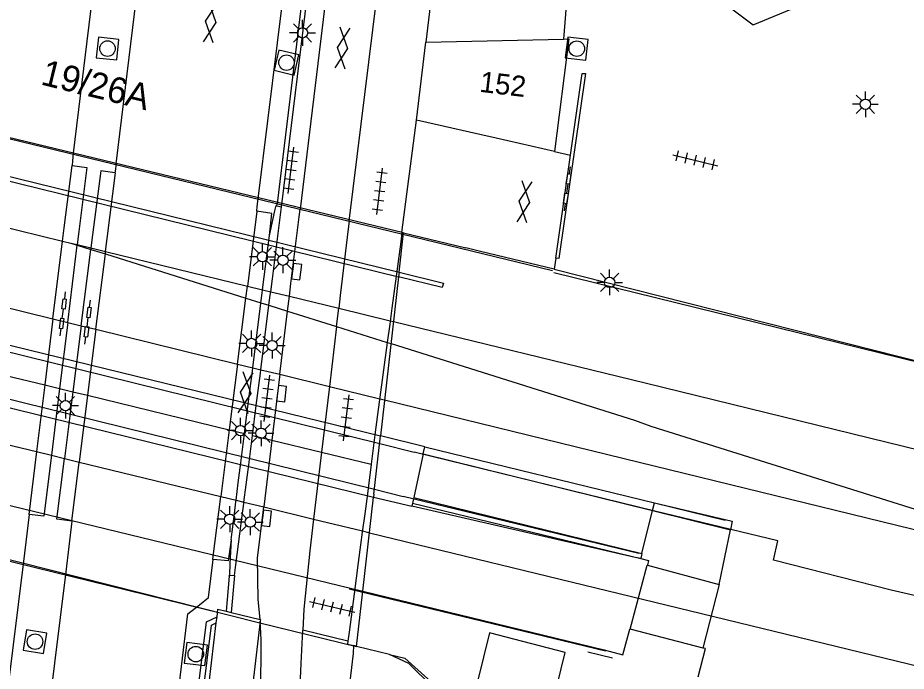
# Model space of a CAD drawing. Extents: x 131000 to 133014, y 396499 to 399001.
# Drawn here: x 131700.07 to 131743.05, y 397381.73 to 397413.33 of the extents above; entities that cross this region are included whole.
import ezdxf

# ---------------------------------------------------------------- set-up
doc = ezdxf.new("R2010")
doc.units = 0
for name, color, linetype in [('gg-afsc-hekwerk', 7, 'Continuous'), ('gg-afsc-muur', 7, 'Continuous'), ('gg-anno-huisnummerreeks BGT', 7, 'Continuous'), ('gg-aspt-spoorlijn', 7, 'Continuous'), ('gg-bbg-hoofdgebouw', 7, 'Continuous'), ('gg-bbg-overig bouwwerk', 7, 'Continuous'), ('gg-knt-bronhoudergrens', 7, 'Continuous'), ('gg-knt-bronhoudergrens niveau 01', 7, 'Continuous'), ('gg-knt-trap', 7, 'Continuous'), ('gg-knt-verharding', 7, 'Continuous'), ('gg-knt-verharding niveau 01', 7, 'Continuous'), ('gg-knt-verharding nz', 7, 'Continuous'), ('gg-kntw-beschoeiing', 7, 'Continuous'), ('gg-kwrk-kunstwerk', 7, 'Continuous'), ('gg-kwrk-kunstwerk niveau 01', 7, 'Continuous'), ('gt-anno-nummer portaalmast', 7, 'Continuous'), ('gt-grn-afwateringsgoot', 7, 'Continuous'), ('gt-grn-bladgrens', 7, 'Continuous'), ('gt-grn-weggrens', 7, 'Continuous'), ('gt-symb-afwateringsgoot', 7, 'Continuous'), ('gt-symb-gesloten verharding', 7, 'Continuous'), ('gt-symb-kolk', 7, 'Continuous'), ('gt-symb-lichtmast', 7, 'Continuous'), ('gt-symb-rioolschacht', 7, 'Continuous'), ('gt-symb-tegel verharding', 7, 'Continuous'), ('gx-grn-maaiveld', 7, 'Continuous'), ('gx-knt-lijn weginrichtingselement', 7, 'Continuous')]:
    doc.layers.add(name, color=color, linetype=linetype)

# ---------------------------------------------------------------- blocks, each defined once
blk = doc.blocks.new('gt0-LMAST')
at = {"layer": 'gt-symb-lichtmast'}
for p, q in [((-0.182, 0.173), (-0.447, 0.438)), ((-0.005, 0.246), (-0.005, 0.621)), ((0.172, 0.173), (0.437, 0.438)), ((-0.255, -0.004), (-0.63, -0.004)), ((-0.182, -0.181), (-0.447, -0.446)), ((-0.005, -0.254), (-0.005, -0.629)), ((0.437, -0.446), (0.172, -0.181)), ((0.245, -0.004), (0.62, -0.004))]:
    blk.add_line(p, q, dxfattribs=at)
blk.add_circle((-0.005, -0.004), 0.25, dxfattribs=at)
blk = doc.blocks.new('gt0-RS')
at = {"layer": 'gt-symb-rioolschacht'}
blk.add_lwpolyline([(-0.5, -0.5), (0.5, -0.5), (0.5, 0.5), (-0.5, 0.5)], close=True, dxfattribs=at)
blk.add_circle((0, 0), 0.375, dxfattribs=at)
blk = doc.blocks.new('gt0-GESVH1')
at = {"layer": 'gt-symb-gesloten verharding'}
for p, q in [((-0.992, -0.261), (0.008, 0.239)), ((0.008, -0.261), (-0.992, 0.239)), ((0.008, 0.239), (1.008, -0.261)), ((1.008, 0.239), (0.008, -0.261))]:
    blk.add_line(p, q, dxfattribs=at)
blk = doc.blocks.new('gt0-AFWGT_1')
at = {"layer": 'gt-symb-afwateringsgoot'}
for p, q in [((-1.076, 0), (-0.726, 0)), ((-0.225, 0), (0.225, 0)), ((0.725, 0), (1.075, 0))]:
    blk.add_line(p, q, dxfattribs=at)
for points in [[(-0.726, 0.075), (-0.225, 0.075), (-0.225, -0.075), (-0.726, -0.075)], [(0.225, 0.075), (0.725, 0.075), (0.725, -0.075), (0.225, -0.075)]]:
    blk.add_lwpolyline(points, close=True, dxfattribs=at)
blk = doc.blocks.new('gt0-TEG1')
at = {"layer": 'gt-symb-tegel verharding'}
for p, q in [((-1.125, 0), (1.125, 0)), ((-0.9, -0.25), (-0.9, 0.25)), ((-0.45, -0.25), (-0.45, 0.25)), ((0, -0.25), (0, 0.25)), ((0.45, -0.25), (0.45, 0.25)), ((0.9, -0.25), (0.9, 0.25))]:
    blk.add_line(p, q, dxfattribs=at)
blk = doc.blocks.new('gt0-KOLK')
at = {"layer": 'gt-symb-kolk'}
blk.add_lwpolyline([(0, 0), (0.375, 0), (0.375, 0.4), (-0.375, 0.4), (-0.375, 0), (0, 0)], dxfattribs=at)

msp = doc.modelspace()

# ---------------------------------------------------------------- linework, layer by layer
at = {"layer": 'gg-afsc-hekwerk'}
for p, q in [((131717.574, 397392.739), (131719.242, 397392.327)), ((131717.324, 397390.534), (131718.712, 397390.175)), ((131730.112, 397387.429), (131718.712, 397390.175)), ((131727.643, 397382.676), (131728.841, 397382.383))]:
    msp.add_line(p, q, dxfattribs=at)
for points in [[(131773.803, 397387.731), (131764.361, 397390.805), (131762.176, 397392.112), (131757.298, 397393.292), (131742.728, 397396.881), (131725.995, 397401.003)], [(131736.842, 397388.039), (131730.884, 397389.465), (131719.242, 397392.327)], [(131779.947, 397376.463), (131765.767, 397379.945), (131756.358, 397382.28), (131749.326, 397384.036), (131749.202, 397383.503), (131747.851, 397383.857), (131747.991, 397384.345), (131742.325, 397385.649), (131736.618, 397387.108), (131736.842, 397388.039)]]:
    msp.add_lwpolyline(points, dxfattribs=at)
at = {"layer": 'gg-afsc-muur'}
for p, q in [((131714.708, 397421.488), (131712.611, 397404.357)), ((131712.841, 397404.301), (131714.948, 397421.519)), ((131712.597, 397404.241), (131712.611, 397404.357)), ((131712.597, 397404.241), (131712.827, 397404.189)), ((131712.794, 397403.932), (131712.827, 397404.189)), ((131712.827, 397404.189), (131712.841, 397404.301)), ((131712.384, 397400.707), (131712.794, 397403.932)), ((131712.305, 397400.085), (131712.384, 397400.707)), ((131712.22, 397399.429), (131712.283, 397399.917)), ((131712.283, 397399.917), (131712.305, 397400.085)), ((131711.825, 397396.315), (131712.22, 397399.429)), ((131711.727, 397395.554), (131711.804, 397396.153)), ((131711.804, 397396.153), (131711.825, 397396.315)), ((131711.603, 397394.576), (131711.727, 397395.554)), ((131711.42, 397393.137), (131711.603, 397394.576)), ((131711.239, 397391.712), (131711.42, 397393.137)), ((131719.755, 397392.586), (131730.865, 397389.872)), ((131711.116, 397390.748), (131711.239, 397391.712)), ((131711.009, 397389.91), (131711.116, 397390.748)), ((131711, 397389.837), (131711.009, 397389.91)), ((131710.925, 397389.247), (131711, 397389.837)), ((131719.169, 397389.865), (131730.201, 397387.176)), ((131730.865, 397389.872), (131734.291, 397389.035)), ((131710.814, 397388.376), (131710.925, 397389.247)), ((131710.623, 397386.875), (131710.814, 397388.376)), ((131710.557, 397386.362), (131710.623, 397386.875)), ((131710.301, 397386.326), (131710.148, 397384.633)), ((131710.301, 397386.326), (131710.302, 397386.375)), ((131710.557, 397386.362), (131710.394, 397384.572)), ((131716.099, 397385.714), (131728.496, 397382.719))]:
    msp.add_line(p, q, dxfattribs=at)
for points in [[(131707.202, 397367.988), (131709.204, 397384.118), (131709.705, 397384.368)], [(131707.723, 397370.16), (131709.436, 397383.954), (131709.67, 397384.071)]]:
    msp.add_lwpolyline(points, dxfattribs=at)
at = {"layer": 'gg-aspt-spoorlijn'}
for p, q in [((131698.809, 397403.367), (131702.237, 397402.535)), ((131702.237, 397402.535), (131702.639, 397402.437)), ((131702.639, 397402.437), (131702.946, 397402.362)), ((131702.639, 397402.437), (131702.943, 397402.341)), ((131702.946, 397402.362), (131703.609, 397402.201)), ((131702.943, 397402.341), (131703.601, 397402.135)), ((131703.601, 397402.135), (131704.303, 397401.914)), ((131703.609, 397402.201), (131704.317, 397402.029)), ((131704.317, 397402.029), (131711.176, 397400.36)), ((131704.303, 397401.914), (131711.104, 397399.779)), ((131711.176, 397400.36), (131711.908, 397400.182)), ((131711.908, 397400.182), (131712.305, 397400.085)), ((131712.305, 397400.085), (131713.206, 397399.866)), ((131713.206, 397399.866), (131715.594, 397399.285)), ((131698.338, 397399.615), (131701.77, 397398.775)), ((131711.104, 397399.779), (131711.829, 397399.551)), ((131711.829, 397399.551), (131712.22, 397399.429)), ((131712.22, 397399.429), (131713.118, 397399.147)), ((131713.118, 397399.147), (131715.489, 397398.402)), ((131715.594, 397399.285), (131718.081, 397398.68)), ((131701.77, 397398.775), (131702.484, 397398.601)), ((131702.484, 397398.601), (131703.135, 397398.442)), ((131718.081, 397398.68), (131718.245, 397398.64)), ((131718.245, 397398.64), (131730.419, 397395.679)), ((131703.135, 397398.442), (131703.847, 397398.267)), ((131703.847, 397398.267), (131710.701, 397396.59)), ((131715.489, 397398.402), (131717.941, 397397.632)), ((131717.941, 397397.632), (131718.124, 397397.575)), ((131718.124, 397397.575), (131729.909, 397393.874)), ((131710.701, 397396.59), (131711.434, 397396.411)), ((131711.434, 397396.411), (131711.825, 397396.315)), ((131711.825, 397396.315), (131712.741, 397396.091)), ((131712.741, 397396.091), (131715.144, 397395.503)), ((131715.144, 397395.503), (131717.578, 397394.908)), ((131717.578, 397394.908), (131717.814, 397394.85)), ((131717.814, 397394.85), (131730.13, 397391.837)), ((131729.909, 397393.874), (131730.687, 397393.578)), ((131730.687, 397393.578), (131757.904, 397385.057)), ((131697.533, 397393.187), (131700.973, 397392.351)), ((131700.973, 397392.351), (131701.694, 397392.175)), ((131701.694, 397392.175), (131702.323, 397392.022)), ((131702.323, 397392.022), (131703.042, 397391.847)), ((131703.042, 397391.847), (131709.893, 397390.181)), ((131730.13, 397391.837), (131757.904, 397385.057)), ((131709.893, 397390.181), (131710.63, 397390.002)), ((131710.63, 397390.002), (131711.009, 397389.91)), ((131711.009, 397389.91), (131711.966, 397389.677)), ((131711.966, 397389.677), (131714.38, 397389.09)), ((131714.38, 397389.09), (131716.741, 397388.515)), ((131716.741, 397388.515), (131717.084, 397388.432)), ((131717.084, 397388.432), (131729.758, 397385.349)), ((131729.758, 397385.349), (131733.135, 397384.528))]:
    msp.add_line(p, q, dxfattribs=at)
for points in [[(131730.419, 397395.679), (131868.942, 397361.737), (131903.166, 397353.165), (132046.719, 397318.202), (132097.768, 397305.577)], [(131733.135, 397384.528), (131744.941, 397381.656), (131764.841, 397376.893), (131798.667, 397369.303), (131817.252, 397364.815)]]:
    msp.add_lwpolyline(points, dxfattribs=at)
at = {"layer": 'gg-bbg-hoofdgebouw'}
for p, q in [((131719.8, 397412.16), (131726.47, 397412.304)), ((131726.73, 397412.31), (131726.03, 397406.86)), ((131726.47, 397412.304), (131726.73, 397412.31)), ((131719.36, 397408.39), (131719.8, 397412.16)), ((131722.417, 397407.689), (131719.36, 397408.39)), ((131723.214, 397407.506), (131722.417, 397407.689)), ((131726.03, 397406.86), (131723.214, 397407.506))]:
    msp.add_line(p, q, dxfattribs=at)
at = {"layer": 'gg-bbg-overig bouwwerk'}
msp.add_lwpolyline([(131722.88, 397383.583), (131722.302, 397381.233), (131725.989, 397380.33), (131726.555, 397382.643), (131722.88, 397383.583)], dxfattribs=at)
at = {"layer": 'gg-knt-bronhoudergrens'}
msp.add_line((131716.017, 397383.044), (131716.324, 397382.969), dxfattribs=at)
msp.add_lwpolyline([(131718.048, 397382.549), (131718.789, 397382.368), (131721.171, 397380.227)], dxfattribs=at)
at = {"layer": 'gg-knt-bronhoudergrens niveau 01'}
msp.add_line((131718.733, 397402.927), (131689.368, 397410.01), dxfattribs=at)
at = {"layer": 'gg-knt-trap'}
for p, q in [((131726.03, 397406.86), (131726.806, 397406.682)), ((131726.093, 397401.715), (131726.016, 397401.17)), ((131709.67, 397384.071), (131709.705, 397384.368)), ((131710.148, 397384.633), (131710.394, 397384.572)), ((131710.394, 397384.572), (131711.791, 397384.228))]:
    msp.add_line(p, q, dxfattribs=at)
for points in [[(131709.705, 397384.368), (131709.748, 397384.731), (131710.148, 397384.633)], [(131711.796, 397384.157), (131710.726, 397375.111), (131708.647, 397375.372), (131709.67, 397384.071)], [(131711.791, 397384.228), (131711.804, 397384.225), (131711.796, 397384.157)]]:
    msp.add_lwpolyline(points, dxfattribs=at)
at = {"layer": 'gg-knt-verharding'}
for p, q in [((131716.096, 397403.5), (131718.375, 397421.956)), ((131715.852, 397421.635), (131713.726, 397404.083)), ((131704.819, 397406.276), (131706.556, 397420.446)), ((131704.367, 397420.167), (131702.743, 397406.787)), ((131720.2, 397415.449), (131719.8, 397412.16)), ((131726.672, 397414.918), (131726.47, 397412.304)), ((131726.016, 397401.17), (131762.283, 397392.002))]:
    msp.add_line(p, q, dxfattribs=at)
for points in [[(131741.8, 397421.13), (131737.08, 397424.63), (131731.68, 397422.35), (131730.97, 397416.51), (131735.64, 397412.99), (131741.08, 397415.25), (131741.8, 397421.13)], [(131711.693, 397404.584), (131713.103, 397415.907), (131713.773, 397421.369)], [(131700.341, 397387.044), (131697.077, 397360.779), (131692.466, 397323.47)], [(131702.391, 397386.541), (131696.561, 397339.648), (131694.505, 397323.221)], [(131706.294, 397368.1), (131707.374, 397376.863), (131708.296, 397384.515), (131708.854, 397384.95)], [(131688.977, 397175.895), (131695.768, 397236.721), (131698.684, 397261.926), (131702.395, 397291.921), (131706.062, 397320.94), (131706.521, 397323.397), (131707.158, 397326.366), (131707.496, 397328.872), (131713.356, 397376.669), (131713.67, 397379.572), (131713.771, 397382.099), (131713.856, 397383.722)], [(131715.433, 397375.305), (131716.312, 397382.595), (131716.324, 397382.969)]]:
    msp.add_lwpolyline(points, dxfattribs=at)
msp.add_arc((131689.431, 397382.627), 22.417, 351.7275, 3.9127, dxfattribs=at)
at = {"layer": 'gg-knt-verharding niveau 01'}
for p, q in [((131689.133, 397408.027), (131718.491, 397400.804)), ((131689.16, 397408.251), (131718.517, 397401.028)), ((131718.517, 397401.028), (131718.733, 397402.927)), ((131692.263, 397399.311), (131717.617, 397393.116))]:
    msp.add_line(p, q, dxfattribs=at)
msp.add_lwpolyline([(131691.587, 397396.455), (131702.513, 397393.782), (131717.279, 397390.145)], dxfattribs=at)
at = {"layer": 'gg-knt-verharding nz'}
for p, q in [((131702.743, 397406.787), (131702.711, 397406.423)), ((131702.711, 397406.423), (131702.691, 397406.186)), ((131704.819, 397406.276), (131704.775, 397405.914)), ((131704.775, 397405.914), (131704.766, 397405.84)), ((131711.647, 397404.215), (131711.693, 397404.584)), ((131711.633, 397403.977), (131711.647, 397404.215)), ((131713.68, 397403.712), (131713.726, 397404.083)), ((131712.238, 397402.808), (131712.506, 397404.003)), ((131713.282, 397400.487), (131713.68, 397403.712)), ((131716.096, 397403.5), (131716.052, 397403.127)), ((131711.986, 397400.804), (131712.238, 397402.808)), ((131716.052, 397403.127), (131715.668, 397399.904)), ((131711.908, 397400.182), (131711.986, 397400.804)), ((131713.206, 397399.866), (131713.282, 397400.487)), ((131711.829, 397399.551), (131711.887, 397400.013)), ((131711.887, 397400.013), (131711.908, 397400.182)), ((131713.118, 397399.147), (131713.206, 397399.866)), ((131715.668, 397399.904), (131715.594, 397399.285)), ((131711.434, 397396.411), (131711.827, 397399.532)), ((131711.827, 397399.532), (131711.829, 397399.551)), ((131712.741, 397396.091), (131713.118, 397399.147)), ((131715.489, 397398.402), (131715.594, 397399.285)), ((131715.489, 397398.402), (131715.144, 397395.503)), ((131711.414, 397396.249), (131711.434, 397396.411)), ((131711.339, 397395.649), (131711.414, 397396.249)), ((131712.741, 397396.091), (131712.357, 397392.909)), ((131711.216, 397394.671), (131711.339, 397395.649)), ((131715.144, 397395.503), (131714.765, 397392.323)), ((131711.035, 397393.231), (131711.216, 397394.671)), ((131710.856, 397391.806), (131711.035, 397393.231)), ((131712.357, 397392.909), (131711.966, 397389.677)), ((131714.765, 397392.323), (131714.38, 397389.09)), ((131710.735, 397390.842), (131710.856, 397391.806)), ((131710.63, 397390.002), (131710.735, 397390.842)), ((131710.547, 397389.339), (131710.621, 397389.928)), ((131710.621, 397389.928), (131710.63, 397390.002)), ((131700.618, 397389.309), (131700.341, 397387.044)), ((131710.437, 397388.466), (131710.547, 397389.339)), ((131702.685, 397388.996), (131702.391, 397386.541)), ((131710.39, 397388.092), (131710.437, 397388.466)), ((131710.39, 397388.092), (131710.331, 397386.947)), ((131710.331, 397386.947), (131710.302, 397386.375)), ((131710.302, 397386.375), (131710.557, 397386.362))]:
    msp.add_line(p, q, dxfattribs=at)
for points in [[(131712.506, 397404.003), (131712.561, 397404.249), (131712.597, 397404.241)], [(131711.791, 397384.228), (131711.698, 397385.213), (131711.658, 397387.205), (131711.966, 397389.677)], [(131714.38, 397389.09), (131714.198, 397387.561), (131713.909, 397384.74), (131713.856, 397383.722)], [(131708.854, 397384.95), (131709.292, 397385.292), (131709.521, 397387.129)]]:
    msp.add_lwpolyline(points, dxfattribs=at)
at = {"layer": 'gg-kntw-beschoeiing'}
for p, q in [((131686.144, 397398.212), (131717.324, 397390.534)), ((131695.174, 397398.278), (131717.574, 397392.739))]:
    msp.add_line(p, q, dxfattribs=at)
at = {"layer": 'gg-kwrk-kunstwerk'}
for p, q in [((131722.453, 397402.03), (131721.738, 397402.202)), ((131726.016, 397401.17), (131722.453, 397402.03))]:
    msp.add_line(p, q, dxfattribs=at)
msp.add_lwpolyline([(131721.319, 397379.8), (131718.99, 397382.106), (131718.048, 397382.549)], dxfattribs=at)
at = {"layer": 'gg-kwrk-kunstwerk niveau 01'}
for p, q in [((131718.491, 397400.804), (131717.617, 397393.116)), ((131718.517, 397401.028), (131718.491, 397400.804)), ((131717.297, 397390.3), (131717.616, 397393.109)), ((131717.617, 397393.116), (131717.616, 397393.109)), ((131716.763, 397385.611), (131717.279, 397390.145)), ((131717.297, 397390.3), (131717.279, 397390.145)), ((131716.745, 397385.452), (131716.763, 397385.611)), ((131716.459, 397382.936), (131716.745, 397385.452))]:
    msp.add_line(p, q, dxfattribs=at)
for points in [[(131687.314, 397392.658), (131687.072, 397390.317), (131711.775, 397384.078), (131716.459, 397382.936)], [(131687.323, 397392.744), (131706.6, 397388.063), (131716.763, 397385.611)]]:
    msp.add_lwpolyline(points, dxfattribs=at)
at = {"layer": 'gt-grn-afwateringsgoot'}
for p, q in [((131726.093, 397401.715), (131726.806, 397406.682)), ((131702.316, 397403.168), (131702.691, 397406.186)), ((131711.633, 397403.977), (131711.255, 397400.981)), ((131702.237, 397402.535), (131702.316, 397403.168)), ((131703.024, 397402.995), (131702.946, 397402.362)), ((131703.689, 397402.833), (131703.609, 397402.201)), ((131701.77, 397398.775), (131702.237, 397402.535)), ((131702.946, 397402.362), (131702.943, 397402.341)), ((131704.317, 397402.029), (131704.396, 397402.66)), ((131702.484, 397398.601), (131702.943, 397402.341)), ((131703.135, 397398.442), (131703.601, 397402.135)), ((131703.609, 397402.201), (131703.601, 397402.135)), ((131704.303, 397401.914), (131704.317, 397402.029)), ((131703.847, 397398.267), (131704.303, 397401.914)), ((131726.248, 397401.697), (131726.093, 397401.715)), ((131711.255, 397400.981), (131711.176, 397400.36)), ((131711.104, 397399.779), (131711.176, 397400.36)), ((131710.701, 397396.59), (131711.104, 397399.779)), ((131701.77, 397398.775), (131701.374, 397395.58)), ((131702.484, 397398.601), (131702.091, 397395.406)), ((131703.135, 397398.442), (131702.731, 397395.25)), ((131703.847, 397398.267), (131703.447, 397395.076)), ((131710.701, 397396.59), (131710.3, 397393.409)), ((131701.374, 397395.58), (131700.973, 397392.351)), ((131702.091, 397395.406), (131701.694, 397392.175)), ((131702.731, 397395.25), (131702.323, 397392.022)), ((131703.447, 397395.076), (131703.042, 397391.847)), ((131710.3, 397393.409), (131709.893, 397390.181)), ((131702.685, 397388.996), (131703.042, 397391.847))]:
    msp.add_line(p, q, dxfattribs=at)
for points in [[(131726.806, 397406.682), (131727.375, 397410.644), (131727.526, 397410.646), (131726.248, 397401.697)], [(131702.691, 397406.186), (131703.405, 397406.097), (131703.024, 397402.995)], [(131704.766, 397405.84), (131704.08, 397405.925), (131703.689, 397402.833)], [(131704.396, 397402.66), (131704.794, 397405.836), (131704.766, 397405.84)], [(131712.238, 397402.808), (131712.363, 397403.872), (131711.633, 397403.977)], [(131700.973, 397392.351), (131700.595, 397389.312), (131700.618, 397389.309)], [(131701.694, 397392.175), (131701.332, 397389.229), (131700.618, 397389.309)], [(131702.685, 397388.996), (131701.952, 397389.084), (131702.323, 397392.022)], [(131709.521, 397387.129), (131709.508, 397387.13), (131709.51, 397387.149), (131709.893, 397390.181)], [(131710.39, 397388.092), (131710.243, 397387.067), (131709.521, 397387.129)]]:
    msp.add_lwpolyline(points, dxfattribs=at)
at = {"layer": 'gt-grn-bladgrens'}
for p, q in [((131718.65, 397402.947), (131719.36, 397408.39)), ((131718.733, 397402.927), (131718.65, 397402.947)), ((131716.036, 397383.185), (131713.856, 397383.722)), ((131716.036, 397383.185), (131716.017, 397383.044))]:
    msp.add_line(p, q, dxfattribs=at)
for points in [[(131718.65, 397402.947), (131718.59, 397402.499), (131718.162, 397399.292), (131718.059, 397398.513), (131717.941, 397397.632), (131717.556, 397394.741), (131717.476, 397394.147), (131717.346, 397393.17), (131717.162, 397391.741)], [(131717.162, 397391.741), (131716.978, 397390.311), (131716.851, 397389.346), (131716.733, 397388.455), (131716.653, 397387.849), (131716.54, 397386.996), (131716.338, 397385.467), (131716.094, 397383.627), (131716.036, 397383.185)]]:
    msp.add_lwpolyline(points, dxfattribs=at)
at = {"layer": 'gt-grn-weggrens'}
for p, q in [((131697.937, 397396.416), (131701.374, 397395.58)), ((131701.374, 397395.58), (131702.091, 397395.406)), ((131702.091, 397395.406), (131702.731, 397395.25)), ((131702.731, 397395.25), (131703.447, 397395.076)), ((131703.447, 397395.076), (131710.3, 397393.409)), ((131710.3, 397393.409), (131711.035, 397393.231)), ((131711.42, 397393.137), (131712.357, 397392.909)), ((131712.357, 397392.909), (131714.765, 397392.323)), ((131714.765, 397392.323), (131717.162, 397391.741))]:
    msp.add_line(p, q, dxfattribs=at)
at = {"layer": 'gx-grn-maaiveld'}
for p, q in [((131718.733, 397402.927), (131721.738, 397402.202)), ((131719.755, 397392.586), (131717.616, 397393.109)), ((131719.681, 397392.242), (131719.755, 397392.586)), ((131719.755, 397392.586), (131730.865, 397389.872)), ((131719.681, 397392.242), (131719.226, 397390.129)), ((131719.681, 397392.242), (131730.773, 397389.499)), ((131717.279, 397390.145), (131719.137, 397389.719)), ((131719.226, 397390.129), (131719.137, 397389.719)), ((131719.226, 397390.129), (131730.261, 397387.424)), ((131730.261, 397387.424), (131730.773, 397389.499)), ((131730.773, 397389.499), (131730.865, 397389.872)), ((131730.773, 397389.499), (131734.538, 397388.569)), ((131733.99, 397385.93), (131734.538, 397388.569)), ((131730.261, 397387.424), (131730.201, 397387.176)), ((131730.524, 397386.856), (131733.99, 397385.93)), ((131733.224, 397382.848), (131729.688, 397383.759)), ((131716.459, 397382.936), (131716.324, 397382.969)), ((131718.048, 397382.549), (131716.459, 397382.936))]:
    msp.add_line(p, q, dxfattribs=at)
for points in [[(131718.517, 397401.028), (131720.659, 397400.501), (131720.605, 397400.283), (131718.491, 397400.804)], [(131730.201, 397387.176), (131729.939, 397387.24), (131719.137, 397389.719)], [(131730.865, 397389.872), (131734.632, 397388.983), (131734.538, 397388.569)], [(131730.201, 397387.176), (131730.579, 397387.093), (131730.524, 397386.856)], [(131729.688, 397383.759), (131730.513, 397386.859), (131730.524, 397386.856)], [(131716.763, 397385.611), (131728.436, 397382.765), (131729.337, 397382.524), (131729.669, 397383.764), (131729.688, 397383.759)], [(131733.224, 397382.848), (131734.008, 397385.925), (131733.99, 397385.93)], [(131732.985, 397381.463), (131733.329, 397382.824), (131733.224, 397382.848)]]:
    msp.add_lwpolyline(points, dxfattribs=at)
at = {"layer": 'gx-knt-lijn weginrichtingselement'}
for p, q in [((131683.371, 397411.44), (131725.935, 397401.109)), ((131681.137, 397391.58), (131709.863, 397384.561))]:
    msp.add_line(p, q, dxfattribs=at)

# ---------------------------------------------------------------- block references
at = {"layer": 'gt-symb-afwateringsgoot'}
for p, xscale, yscale, rotation in [((131726.644, 397405.068), 1.0000260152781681, 1.0000260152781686, -98.17061553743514), ((131702.25, 397399.02), 0.9999839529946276, 0.9999839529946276, 82.92739616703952), ((131703.451, 397398.614), 0.9999990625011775, 0.9999990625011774, 82.8625469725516)]:
    msp.add_blockref('gt0-AFWGT_1', p, dxfattribs=dict(at, xscale=xscale, yscale=yscale, rotation=rotation))
at = {"layer": 'gt-symb-gesloten verharding'}
for p, rotation in [((131709.388, 397413.133), 82.93185994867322), ((131715.765, 397411.865), 83.10945167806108), ((131724.562, 397404.427), 82.9318599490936), ((131711.074, 397395.192), 83.16632765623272)]:
    msp.add_blockref('gt0-GESVH1', p, dxfattribs=dict(at, rotation=rotation))
at = {"layer": 'gt-symb-kolk'}
for p, rotation in [((131713.36, 397401.075), -96.94741065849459), ((131712.628, 397395.175), -96.89054832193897), ((131711.902, 397389.147), -97.00425924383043)]:
    msp.add_blockref('gt0-KOLK', p, dxfattribs=dict(at, rotation=rotation))
at = {"layer": 'gt-symb-lichtmast'}
for p in [(131713.847, 397412.608), (131741.075, 397409.154), (131711.908, 397401.78), (131712.898, 397401.613), (131728.704, 397400.54), (131711.385, 397397.587), (131712.376, 397397.488), (131702.377, 397394.579), (131710.848, 397393.372), (131711.839, 397393.243), (131710.325, 397389.088), (131711.319, 397388.949)]:
    msp.add_blockref('gt0-LMAST', p, dxfattribs=at)
at = {"layer": 'gt-symb-rioolschacht'}
for p, rotation in [((131704.408, 397411.844), 173.79902900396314), ((131727.109, 397411.84), -6.776782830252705), ((131713.067, 397411.166), 166.70041567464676), ((131700.903, 397383.162), -98.97262661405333), ((131708.679, 397382.56), 172.81812146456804)]:
    msp.add_blockref('gt0-RS', p, dxfattribs=dict(at, rotation=rotation))
at = {"layer": 'gt-symb-tegel verharding'}
for p, rotation in [((131713.285, 397405.959), 82.93185994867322), ((131732.843, 397406.445), -13.772145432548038), ((131717.576, 397404.941), 82.9318599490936), ((131712.124, 397394.926), 83.16632765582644), ((131715.959, 397393.988), 83.16632765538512), ((131715.276, 397384.846), -13.59156043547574)]:
    msp.add_blockref('gt0-TEG1', p, dxfattribs=dict(at, rotation=rotation))

# ---------------------------------------------------------------- texts
at = {"layer": 'gg-anno-huisnummerreeks BGT'}
msp.add_text('152', height=1, rotation=353.3, dxfattribs=at).set_placement((131722.374, 397409.757))
at = {"layer": 'gt-anno-nummer portaalmast'}
msp.add_text('19/26A', height=1.25, rotation=346.2279, dxfattribs=at).set_placement((131701.129, 397410.116))

doc.saveas('drawing.dxf')
